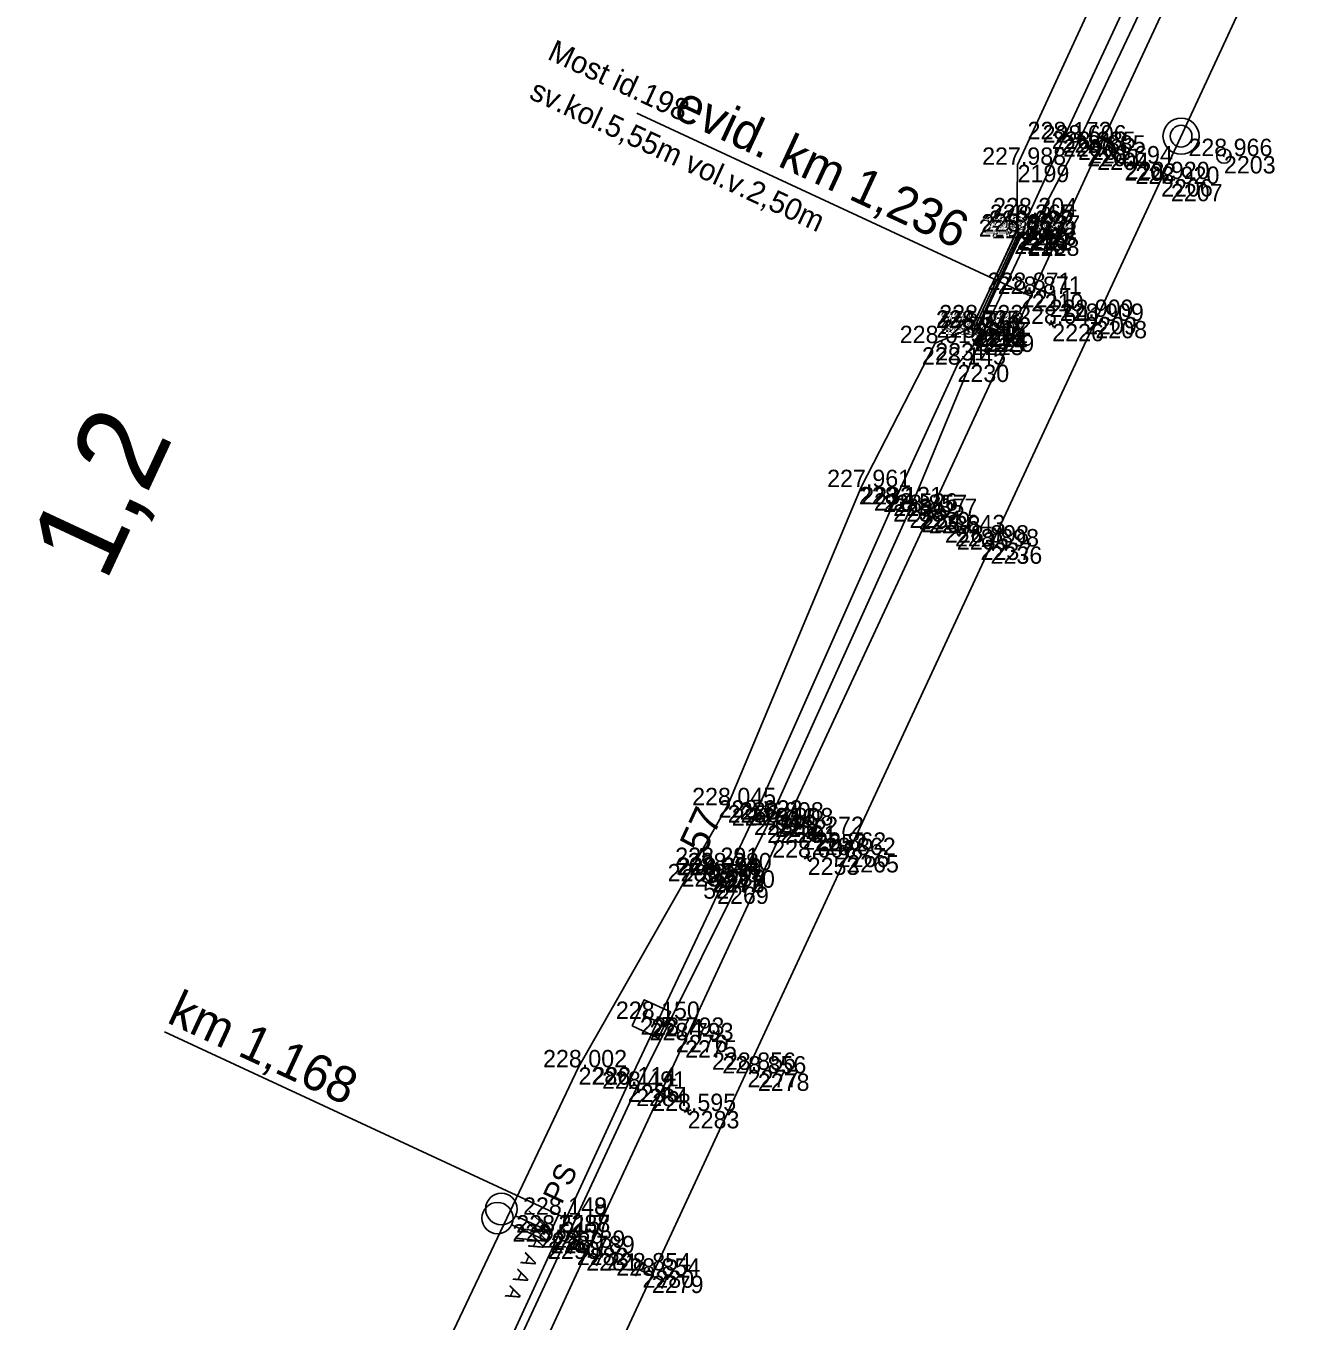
# Model space of a CAD drawing. Extents: x -644425 to -644066, y -1046154 to -1045540.
# Drawn here: x -644261.9 to -644173.8, y -1045807.6 to -1045718.1 of the extents above; entities that cross this region are included whole.
import ezdxf

# ---------------------------------------------------------------- set-up
doc = ezdxf.new("R2010")
doc.units = 0
for name, color, linetype in [('Vrstva 1', 7, 'Continuous'), ('Vrstva 11', 7, 'Continuous'), ('Vrstva 12', 7, 'Continuous'), ('Vrstva 17', 7, 'Continuous'), ('Vrstva 18', 7, 'Continuous'), ('Vrstva 23', 7, 'Continuous'), ('Vrstva 3', 7, 'Continuous'), ('Vrstva 33', 7, 'Continuous'), ('Vrstva 36', 7, 'Continuous'), ('Vrstva 4', 7, 'Continuous'), ('Vrstva 49', 7, 'Continuous'), ('Vrstva 6', 7, 'Continuous'), ('Vrstva 60', 7, 'Continuous'), ('Vrstva 61', 7, 'Continuous'), ('Vrstva 62', 7, 'Continuous'), ('Vrstva 7', 7, 'Continuous')]:
    doc.layers.add(name, color=color, linetype=linetype)

msp = doc.modelspace()

# ---------------------------------------------------------------- linework, layer by layer
at = {"layer": 'Vrstva 1'}
for points in [[(-644261.901, -1045886.221), (-644253.569, -1045868.297), (-644247.836, -1045855.914), (-644238.681, -1045836.231), (-644229.248, -1045815.935), (-644223.2, -1045802.861), (-644216.377, -1045788.159), (-644209.485, -1045773.317), (-644199.546, -1045751.952), (-644192.432, -1045736.616), (-644187.91, -1045726.866), (-644178.385, -1045706.377), (-644167.718, -1045683.409), (-644162.734, -1045672.675), (-644153.238, -1045652.212), (-644143.755, -1045631.805), (-644136.162, -1045615.435), (-644132.181, -1045606.849), (-644125.381, -1045592.193), (-644118.954, -1045578.357), (-644111.363, -1045561.995), (-644101.68, -1045541.123)], [(-644257.584, -1045888.203), (-644249.371, -1045870.516), (-644243.125, -1045857.066), (-644234.387, -1045838.241), (-644224.947, -1045817.925), (-644218.675, -1045804.414), (-644212.068, -1045790.199), (-644205.182, -1045775.37), (-644195.283, -1045754.057), (-644188.043, -1045738.485), (-644183.505, -1045728.694), (-644173.985, -1045708.194), (-644163.21, -1045685.027), (-644158.475, -1045674.84), (-644148.943, -1045654.317), (-644139.462, -1045633.909), (-644131.76, -1045617.29), (-644127.604, -1045608.33), (-644121.08, -1045594.295), (-644114.622, -1045580.381), (-644107.041, -1045564.054), (-644097.302, -1045543.081)]]:
    msp.add_lwpolyline(points, dxfattribs=at)
at = {"layer": 'Vrstva 11'}
for p, q in [((-644214.56, -1045777.218), (-644214.874, -1045776.36)), ((-644214.206, -1045777.096), (-644214.524, -1045776.226))]:
    msp.add_line(p, q, dxfattribs=at)
msp.add_circle((-644214.533, -1045776.722), 0.5, dxfattribs=at)
at = {"layer": 'Vrstva 12'}
msp.add_lwpolyline([(-644214.701, -1045776.053), (-644213.746, -1045776.424), (-644214.167, -1045777.543), (-644215.126, -1045777.183), (-644214.701, -1045776.053)], dxfattribs=at)
at = {"layer": 'Vrstva 17'}
msp.add_line((-644193.329, -1045732.388), (-644196.414, -1045739.009), dxfattribs=at)
at = {"layer": 'Vrstva 18'}
for p, q in [((-644192.502, -1045736.768), (-644219.717, -1045724.144)), ((-644193.465, -1045732.309), (-644193.467, -1045732.314)), ((-644196.601, -1045738.983), (-644196.583, -1045738.952))]:
    msp.add_line(p, q, dxfattribs=at)
msp.add_lwpolyline([(-644196.282, -1045739.093), (-644196.583, -1045738.952), (-644196.38, -1045738.582), (-644193.644, -1045732.663), (-644193.467, -1045732.314), (-644193.215, -1045732.434), (-644196.282, -1045739.093), (-644196.601, -1045738.983), (-644193.465, -1045732.309), (-644193.215, -1045732.434)], dxfattribs=at)
at = {"layer": 'Vrstva 23'}
for p, q in [((-644214.442, -1045776.763), (-644214.442, -1045776.763)), ((-644225.115, -1045800.208), (-644225.115, -1045800.208))]:
    msp.add_line(p, q, dxfattribs=at)
at = {"layer": 'Vrstva 3'}
for p, q in [((-644225.579, -1045801.433), (-644228.083, -1045800.271)), ((-644225.845, -1045802.058), (-644228.351, -1045800.899)), ((-644224.318, -1045802.895), (-644223.898, -1045801.987)), ((-644224.108, -1045802.441), (-644222.292, -1045803.281)), ((-644222.502, -1045803.735), (-644222.082, -1045802.827)), ((-644219.371, -1045803.539), (-644219.793, -1045804.446)), ((-644217.768, -1045804.835), (-644219.582, -1045803.993)), ((-644217.557, -1045804.382), (-644217.979, -1045805.289))]:
    msp.add_line(p, q, dxfattribs=at)
for points in [[(-644227.747, -1045801.187), (-644225.579, -1045801.433), (-644227.166, -1045799.936)], [(-644228.013, -1045801.815), (-644225.845, -1045802.058), (-644227.434, -1045800.563)]]:
    msp.add_lwpolyline(points, dxfattribs=at)
for centre in [(-644229.333, -1045800.44), (-644229.065, -1045799.811)]:
    msp.add_circle(centre, 1.084, dxfattribs=at)
at = {"layer": 'Vrstva 33'}
for p, q in [((-644219.373, -1045786.926), (-644218.952, -1045786.019)), ((-644219.162, -1045786.472), (-644218.256, -1045786.894))]:
    msp.add_line(p, q, dxfattribs=at)
msp.add_lwpolyline([(-644220.037, -1045787.169), (-644219.195, -1045785.355), (-644217.381, -1045786.197), (-644218.223, -1045788.011), (-644220.037, -1045787.169)], dxfattribs=at)
at = {"layer": 'Vrstva 36'}
msp.add_lwpolyline([(-644192.872, -1045731.642), (-644192.916, -1045732.057), (-644196.315, -1045739.383), (-644196.567, -1045739.646)], dxfattribs=at)
at = {"layer": 'Vrstva 4'}
for points in [[(-644105.766, -1045544.277), (-644116.317, -1045566.809), (-644128.289, -1045592.92), (-644131.605, -1045599.431), (-644134.411, -1045605.524), (-644146.947, -1045632.246), (-644154.555, -1045649.587), (-644165.036, -1045671.648), (-644170.046, -1045682.443), (-644180.468, -1045704.853), (-644190.276, -1045725.939), (-644192.655, -1045731.189), (-644192.715, -1045732.791)], [(-644104.834, -1045544.563), (-644115.413, -1045567.247), (-644126.587, -1045591.732), (-644133.491, -1045605.948), (-644145.843, -1045632.821), (-644153.921, -1045650.606), (-644164.187, -1045672.05), (-644168.981, -1045682.753), (-644179.404, -1045705.412), (-644189.238, -1045726.165), (-644192.715, -1045732.791), (-644195.836, -1045739.428), (-644200.882, -1045751.585), (-644210.701, -1045773.33), (-644219.755, -1045791.506), (-644230.982, -1045815.664), (-644240.426, -1045836.077), (-644246.865, -1045849.967)], [(-644195.836, -1045739.428), (-644197.566, -1045741.505), (-644202.013, -1045751.146), (-644211.62, -1045772.786), (-644220.336, -1045791.214), (-644231.427, -1045815.294), (-644241.106, -1045835.692), (-644246.388, -1045847.292), (-644246.865, -1045849.967)]]:
    msp.add_lwpolyline(points, dxfattribs=at)
at = {"layer": 'Vrstva 49'}
for p, q in [((-644186.275, -1045727.694), (-644185.805, -1045727.522)), ((-644185.954, -1045727.843), (-644186.126, -1045727.373)), ((-644190.936, -1045738.926), (-644191.108, -1045738.456)), ((-644191.257, -1045738.777), (-644190.787, -1045738.605)), ((-644197.524, -1045753.313), (-644197.696, -1045752.843)), ((-644197.845, -1045753.164), (-644197.375, -1045752.992)), ((-644208.145, -1045775.627), (-644207.675, -1045775.455)), ((-644207.824, -1045775.776), (-644207.996, -1045775.306)), ((-644216.43, -1045793.13), (-644215.96, -1045792.958)), ((-644216.109, -1045793.279), (-644216.281, -1045792.809))]:
    msp.add_line(p, q, dxfattribs=at)
for points in [[(-644108.28, -1045543.261), (-644118.745, -1045565.863), (-644130.155, -1045590.223), (-644133.537, -1045597.374), (-644136.707, -1045603.056), (-644137.059, -1045604.255), (-644149.203, -1045630.48), (-644158.166, -1045649.719), (-644167.872, -1045670.554), (-644172.45, -1045681.187), (-644183.453, -1045704.158), (-644187.348, -1045711.688), (-644187.993, -1045715.927), (-644193.412, -1045727.705), (-644193.467, -1045732.314)], [(-644196.583, -1045738.952), (-644199.102, -1045740.018), (-644204.211, -1045749.961), (-644213.435, -1045771.927), (-644223.738, -1045790.026), (-644235.159, -1045814.071), (-644245.361, -1045833.069)]]:
    msp.add_lwpolyline(points, dxfattribs=at)
at = {"layer": 'Vrstva 6'}
for p, q in [((-644225.117, -1045800.209), (-644252.329, -1045787.58)), ((-644225.951, -1045802.005), (-644225.117, -1045800.209)), ((-644224.663, -1045800.419), (-644225.571, -1045799.999))]:
    msp.add_line(p, q, dxfattribs=at)
at = {"layer": 'Vrstva 60'}
for p, q in [((-644190.276, -1045725.939), (-644190.276, -1045725.939)), ((-644189.238, -1045726.165), (-644189.238, -1045726.165)), ((-644188.603, -1045726.606), (-644188.603, -1045726.606)), ((-644187.91, -1045726.866), (-644187.91, -1045726.866)), ((-644193.412, -1045727.705), (-644193.412, -1045727.705)), ((-644186.04, -1045727.608), (-644186.04, -1045727.608)), ((-644179.165, -1045727.103), (-644179.165, -1045727.103)), ((-644183.505, -1045728.694), (-644183.505, -1045728.694)), ((-644182.825, -1045729.024), (-644182.825, -1045729.024)), ((-644192.655, -1045731.189), (-644192.655, -1045731.189)), ((-644193.467, -1045732.314), (-644193.467, -1045732.314)), ((-644193.465, -1045732.309), (-644193.465, -1045732.309)), ((-644192.916, -1045732.057), (-644192.916, -1045732.057)), ((-644192.872, -1045731.642), (-644192.872, -1045731.642)), ((-644193.644, -1045732.663), (-644193.644, -1045732.663)), ((-644193.329, -1045732.388), (-644193.329, -1045732.388)), ((-644193.215, -1045732.434), (-644193.215, -1045732.434)), ((-644192.715, -1045732.791), (-644192.715, -1045732.791)), ((-644193.134, -1045736.348), (-644193.134, -1045736.348)), ((-644192.432, -1045736.616), (-644192.432, -1045736.616)), ((-644196.38, -1045738.582), (-644196.38, -1045738.582)), ((-644188.753, -1045738.21), (-644188.753, -1045738.21)), ((-644188.043, -1045738.485), (-644188.043, -1045738.485)), ((-644196.601, -1045738.983), (-644196.601, -1045738.983)), ((-644196.583, -1045738.952), (-644196.583, -1045738.952)), ((-644196.414, -1045739.009), (-644196.414, -1045739.009)), ((-644196.315, -1045739.383), (-644196.315, -1045739.383)), ((-644196.282, -1045739.093), (-644196.282, -1045739.093)), ((-644195.836, -1045739.428), (-644195.836, -1045739.428)), ((-644191.022, -1045738.691), (-644191.022, -1045738.691)), ((-644199.102, -1045740.018), (-644199.102, -1045740.018)), ((-644196.567, -1045739.646), (-644196.567, -1045739.646)), ((-644197.566, -1045741.505), (-644197.566, -1045741.505)), ((-644204.211, -1045749.961), (-644204.211, -1045749.961)), ((-644202.013, -1045751.146), (-644202.013, -1045751.146)), ((-644200.882, -1045751.585), (-644200.882, -1045751.585)), ((-644200.246, -1045751.681), (-644200.246, -1045751.681)), ((-644199.546, -1045751.952), (-644199.546, -1045751.952)), ((-644197.61, -1045753.078), (-644197.61, -1045753.078)), ((-644195.976, -1045753.791), (-644195.976, -1045753.791)), ((-644195.283, -1045754.057), (-644195.283, -1045754.057)), ((-644213.435, -1045771.927), (-644213.435, -1045771.927)), ((-644211.62, -1045772.786), (-644211.62, -1045772.786)), ((-644210.701, -1045773.33), (-644210.701, -1045773.33)), ((-644210.147, -1045772.92), (-644210.147, -1045772.92)), ((-644209.485, -1045773.317), (-644209.485, -1045773.317)), ((-644207.38, -1045773.919), (-644207.38, -1045773.919)), ((-644205.843, -1045775.003), (-644205.843, -1045775.003)), ((-644214.701, -1045776.053), (-644214.701, -1045776.053)), ((-644207.91, -1045775.541), (-644207.91, -1045775.541)), ((-644205.182, -1045775.37), (-644205.182, -1045775.37)), ((-644214.533, -1045776.722), (-644214.533, -1045776.722)), ((-644213.746, -1045776.424), (-644213.746, -1045776.424)), ((-644215.126, -1045777.183), (-644215.126, -1045777.183)), ((-644214.167, -1045777.543), (-644214.167, -1045777.543)), ((-644218.709, -1045786.683), (-644218.709, -1045786.683)), ((-644217.011, -1045787.782), (-644217.011, -1045787.782)), ((-644216.377, -1045788.159), (-644216.377, -1045788.159)), ((-644223.738, -1045790.026), (-644223.738, -1045790.026)), ((-644212.068, -1045790.199), (-644212.068, -1045790.199)), ((-644211.355, -1045790.453), (-644211.355, -1045790.453)), ((-644220.336, -1045791.214), (-644220.336, -1045791.214)), ((-644219.755, -1045791.506), (-644219.755, -1045791.506)), ((-644216.195, -1045793.044), (-644216.195, -1045793.044)), ((-644225.117, -1045800.209), (-644225.117, -1045800.209)), ((-644225.845, -1045802.058), (-644225.845, -1045802.058)), ((-644225.579, -1045801.433), (-644225.579, -1045801.433)), ((-644223.855, -1045802.488), (-644223.855, -1045802.488)), ((-644223.2, -1045802.861), (-644223.2, -1045802.861)), ((-644219.323, -1045804.051), (-644219.323, -1045804.051)), ((-644218.675, -1045804.414), (-644218.675, -1045804.414))]:
    msp.add_line(p, q, dxfattribs=at)
at = {"layer": 'Vrstva 62'}
for p, q in [((-644188.603, -1045726.606), (-644188.603, -1045726.606)), ((-644182.825, -1045729.024), (-644182.825, -1045729.024)), ((-644193.134, -1045736.348), (-644193.134, -1045736.348)), ((-644188.753, -1045738.21), (-644188.753, -1045738.21)), ((-644200.246, -1045751.681), (-644200.246, -1045751.681)), ((-644195.976, -1045753.791), (-644195.976, -1045753.791)), ((-644210.147, -1045772.92), (-644210.147, -1045772.92)), ((-644205.843, -1045775.003), (-644205.843, -1045775.003)), ((-644217.011, -1045787.782), (-644217.011, -1045787.782)), ((-644211.355, -1045790.453), (-644211.355, -1045790.453)), ((-644223.855, -1045802.488), (-644223.855, -1045802.488)), ((-644219.323, -1045804.051), (-644219.323, -1045804.051))]:
    msp.add_line(p, q, dxfattribs=at)
at = {"layer": 'Vrstva 7'}
for p, q in [((-644179.145, -1045727.057), (-644179.185, -1045727.149)), ((-644207.401, -1045773.964), (-644207.359, -1045773.874))]:
    msp.add_line(p, q, dxfattribs=at)
for centre, radius in [((-644182.127, -1045725.727), 1.246), ((-644182.127, -1045725.727), 0.752), ((-644179.165, -1045727.103), 0.5), ((-644209.341, -1045773.007), 0.75), ((-644207.38, -1045773.919), 0.5)]:
    msp.add_circle(centre, radius, dxfattribs=at)

# ---------------------------------------------------------------- texts
at = {"layer": 'Vrstva 11'}
msp.add_text('57', height=2, rotation=65.09183, dxfattribs=at).set_placement((-644215.019, -1045775.394))
at = {"layer": 'Vrstva 18'}
for s, height, p in [('Most id.198', 1.5, (-644225.964, -1045720.375)), ('sv.kol.5,55m vol.v.2,50m', 1.5, (-644227.227, -1045723.096)), ('evid. km 1,236', 2.5, (-644217.307, -1045724.391))]:
    msp.add_text(s, height=height, rotation=335.11455, dxfattribs=at).set_placement(p)
at = {"layer": 'Vrstva 6'}
for s, height, rotation, p in [('km 1,168', 2.5, 335.10462, (-644252.25, -1045786.898)), ('PS', 1.5, 65.10462, (-644224.894, -1045799.547)), ('  A A A A A ', 1, 245.10462, (-644226.024, -1045799.788))]:
    msp.add_text(s, height=height, rotation=rotation, dxfattribs=at).set_placement(p)
at = {"layer": 'Vrstva 60'}
for s, p in [('2200', (-644190.276, -1045727.139)), ('2201', (-644189.238, -1045727.365)), ('2205', (-644188.603, -1045727.806)), ('2204', (-644187.91, -1045728.066)), ('2199', (-644193.412, -1045728.905)), ('2202', (-644186.04, -1045728.808)), ('2203', (-644179.165, -1045728.303)), ('2206', (-644183.505, -1045729.894)), ('2207', (-644182.825, -1045730.224)), ('2227', (-644192.655, -1045732.389)), ('2219', (-644193.467, -1045733.514)), ('2220', (-644193.465, -1045733.509)), ('2223', (-644192.916, -1045733.257)), ('2222', (-644192.872, -1045732.842)), ('2218', (-644193.644, -1045733.863)), ('2212', (-644193.329, -1045733.588)), ('2221', (-644193.215, -1045733.634)), ('2228', (-644192.715, -1045733.991)), ('2211', (-644193.134, -1045737.548)), ('2210', (-644192.432, -1045737.816)), ('2217', (-644196.38, -1045739.782)), ('2209', (-644188.753, -1045739.41)), ('2208', (-644188.043, -1045739.685)), ('2215', (-644196.601, -1045740.183)), ('2216', (-644196.583, -1045740.152)), ('2213', (-644196.414, -1045740.209)), ('2224', (-644196.315, -1045740.583)), ('2214', (-644196.282, -1045740.293)), ('2229', (-644195.836, -1045740.628)), ('2226', (-644191.022, -1045739.891)), ('2231', (-644199.102, -1045741.218)), ('2225', (-644196.567, -1045740.846)), ('2230', (-644197.566, -1045742.705)), ('2232', (-644204.211, -1045751.161)), ('2233', (-644202.013, -1045752.346)), ('2234', (-644200.882, -1045752.785)), ('2239', (-644200.246, -1045752.881)), ('2238', (-644199.546, -1045753.152)), ('2235', (-644197.61, -1045754.278)), ('2237', (-644195.976, -1045754.991)), ('2236', (-644195.283, -1045755.257)), ('2256', (-644213.435, -1045773.127)), ('2255', (-644211.62, -1045773.986)), ('2254', (-644210.701, -1045774.53)), ('2262', (-644210.147, -1045774.12)), ('2261', (-644209.485, -1045774.517)), ('2252', (-644207.38, -1045775.119)), ('2266', (-644205.843, -1045776.203)), ('2271', (-644214.701, -1045777.253)), ('2253', (-644207.91, -1045776.741)), ('2265', (-644205.182, -1045776.57)), ('2272', (-644214.533, -1045777.922)), ('2273', (-644214.442, -1045777.963)), ('2270', (-644213.746, -1045777.624)), ('52', (-644215.126, -1045778.383)), ('2269', (-644214.167, -1045778.743)), ('2274', (-644218.709, -1045787.883)), ('2276', (-644217.011, -1045788.982)), ('2275', (-644216.377, -1045789.359)), ('2286', (-644223.738, -1045791.226)), ('2277', (-644212.068, -1045791.399)), ('2278', (-644211.355, -1045791.653)), ('2285', (-644220.336, -1045792.414)), ('2284', (-644219.755, -1045792.706)), ('2283', (-644216.195, -1045794.244)), ('2287', (-644225.117, -1045801.409)), ('2288', (-644225.115, -1045801.408)), ('2290', (-644225.845, -1045803.258)), ('2289', (-644225.579, -1045802.633)), ('2282', (-644223.855, -1045803.688)), ('2281', (-644223.2, -1045804.061)), ('2280', (-644219.323, -1045805.251)), ('2279', (-644218.675, -1045805.614))]:
    msp.add_text(s, height=1.2, dxfattribs=at).set_placement(p)
at = {"layer": 'Vrstva 61'}
for s, p in [('228.172', (-644192.724, -1045725.939)), ('228.606', (-644191.69, -1045726.165)), ('228.885', (-644191.059, -1045726.606)), ('228.885', (-644190.366, -1045726.866)), ('228.966', (-644181.617, -1045727.103)), ('227.988', (-644195.866, -1045727.705)), ('228.694', (-644188.491, -1045727.608)), ('228.920', (-644185.956, -1045728.694)), ('228.920', (-644185.276, -1045729.024)), ('228.365', (-644195.328, -1045731.642)), ('228.304', (-644195.106, -1045731.189)), ('228.463', (-644195.919, -1045732.314)), ('228.663', (-644195.917, -1045732.309)), ('229.656', (-644195.781, -1045732.388)), ('228.668', (-644195.669, -1045732.434)), ('228.699', (-644195.37, -1045732.057)), ('228.469', (-644196.098, -1045732.663)), ('228.634', (-644195.166, -1045732.791)), ('228.871', (-644195.491, -1045736.348)), ('228.871', (-644194.789, -1045736.616)), ('228.522', (-644198.828, -1045738.582)), ('228.641', (-644193.379, -1045738.691)), ('228.909', (-644191.207, -1045738.21)), ('228.909', (-644190.497, -1045738.485)), ('228.725', (-644199.057, -1045738.983)), ('228.524', (-644199.034, -1045738.952)), ('228.440', (-644199.018, -1045739.646)), ('229.731', (-644198.771, -1045739.009)), ('228.740', (-644198.766, -1045739.383)), ('228.708', (-644198.736, -1045739.093)), ('228.582', (-644198.284, -1045739.428)), ('228.013', (-644201.554, -1045740.018)), ('228.145', (-644200.022, -1045741.505)), ('227.961', (-644206.568, -1045749.961)), ('228.131', (-644204.37, -1045751.146)), ('228.526', (-644203.334, -1045751.585)), ('228.857', (-644202.698, -1045751.681)), ('228.857', (-644201.998, -1045751.952)), ('228.643', (-644200.062, -1045753.078)), ('228.898', (-644198.43, -1045753.791)), ('228.898', (-644197.737, -1045754.057)), ('228.045', (-644215.891, -1045771.927)), ('228.022', (-644214.068, -1045772.786)), ('228.556', (-644213.153, -1045773.33)), ('228.808', (-644212.601, -1045772.92)), ('228.808', (-644211.939, -1045773.317)), ('229.272', (-644209.828, -1045773.919)), ('228.606', (-644210.362, -1045775.541)), ('228.862', (-644208.291, -1045775.003)), ('228.862', (-644207.63, -1045775.37)), ('228.291', (-644217.058, -1045776.053)), ('228.280', (-644216.197, -1045776.424)), ('228.250', (-644217.577, -1045777.183)), ('228.294', (-644216.984, -1045776.722)), ('228.359', (-644216.896, -1045776.763)), ('228.239', (-644216.621, -1045777.543)), ('228.150', (-644221.16, -1045786.683)), ('228.793', (-644219.463, -1045787.782)), ('228.793', (-644218.829, -1045788.159)), ('228.002', (-644226.186, -1045790.026)), ('228.856', (-644214.52, -1045790.199)), ('228.856', (-644213.807, -1045790.453)), ('228.114', (-644222.787, -1045791.214)), ('228.491', (-644222.112, -1045791.506)), ('228.595', (-644218.651, -1045793.044)), ('228.148', (-644227.571, -1045800.209)), ('228.149', (-644227.569, -1045800.208)), ('228.515', (-644228.035, -1045801.433)), ('228.545', (-644228.301, -1045802.058)), ('228.789', (-644226.309, -1045802.488)), ('228.789', (-644225.654, -1045802.861)), ('228.854', (-644221.774, -1045804.051)), ('228.854', (-644221.126, -1045804.414))]:
    msp.add_text(s, height=1.2, dxfattribs=at).set_placement(p)
at = {"layer": 'Vrstva 7'}
msp.add_text('1,2', height=6, rotation=65.05215, dxfattribs=at).set_placement((-644256.403, -1045756.61))

doc.saveas('drawing.dxf')
